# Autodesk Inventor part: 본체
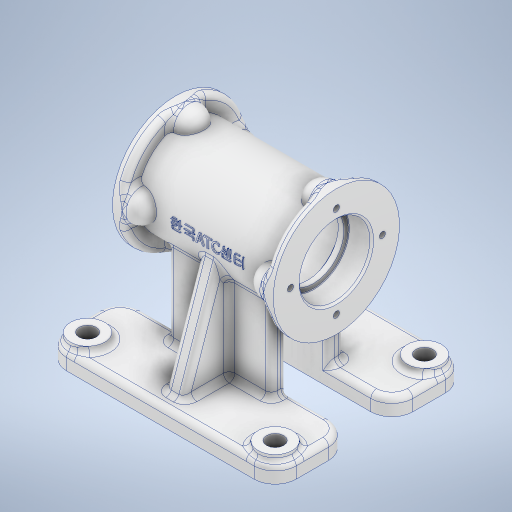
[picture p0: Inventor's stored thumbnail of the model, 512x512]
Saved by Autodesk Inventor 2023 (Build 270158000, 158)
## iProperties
Created: 2026-06
Part Number: 본체
Material: 알루미늄 6061
Document SubType Name: Modeling
Designer: home
Density: 2.7 g/cm^3
Appearance: 알루미늄 - 평지
Mass: 608.577 g
Surface Area: 672.753 cm^2
Volume: 225.399 cm^3
Author: home
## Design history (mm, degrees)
sketch "스케치1"
  geometry: L1 (0, 0)-(-75.914, 0); L2 (-42, 0)-(-42, 33); L3 (-42, 33)-(-37, 33); L4 (-37, 33)-(-37, 25); L5 (-37, 25)-(0, 25); L6 (0, 0)-(0, 52.72); L7 (37, 25)-(0, 25); L8 (37, 33)-(37, 25); L9 (42, 33)-(37, 33); L10 (42, 0)-(42, 33); L11 (-42, 18.5)-(-30, 18.5); L12 (-30, 18.5)-(-30, 16); L13 (-30, 16)-(-27, 16); L14 (-27, 16)-(-27, 20); L15 (-27, 20)-(0, 20); L16 (27, 20)-(0, 20); L17 (27, 16)-(27, 20); L18 (30, 16)-(27, 16); L19 (30, 18.5)-(30, 16); L20 (42, 18.5)-(30, 18.5); 1 further point
  constraints: 40 end point, 9 symmetric about line, 7 perpendicular, 3 point on line, 2 horizontal, 2 vertical
  dimensions: "d0" = 66 diameter of L3 L1; "d1" = 5 distance of L2.end L3.end; "d2" = 50 diameter of L5 L1; "d3" = 42 distance between parallel lines of L6 L2; "d4" = 12 distance of L11.start L11.end; "d6" = 27 distance of L14.end L15.end; "d7" = 37 diameter of L11 L1; "d8" = 32 diameter of L13 L1; "d9" = 40 diameter of L15 L1
revolve "회전1" sketch "스케치1" stored, may be unused: angle "d10" = 90 deg
sketch "스케치2"
  geometry: L1 (37, 25)-(-37, 25) reference; L2 (-37, 33)-(-37, -33) reference; L3 (-37.099, 34.348)-(-37, 34.348); L4 (-37, 33)-(-35, 33); L5 (-27, 25)-(-27, 25); A1 r 8 centre (-35, 25) between (-27, 25) and (-35, 33); 2 further points
  constraints: 6 end point, 2 perpendicular, 2 point on circle, 2 point on line, 2 tangent, 1 centre point, 1 horizontal
  dimensions: "d14" = 8 radius of A1 (derived); "d15" = 10 distance from line of L2 L5.end
revolve "회전2" sketch "스케치2" stored, may be unused: angle "d16" = 210 deg
node "작업 평면1"
sketch "스케치3"
  geometry: L1 (60, -50)-(-60, -50); L2 (-60, -50)-(-60, -11); L3 (-60, -11)-(60, -11); L4 (60, -11)-(60, -50); 2 further points
  constraints: 8 end point, 2 parallel, 1 horizontal, 1 midpoint, 1 perpendicular, 1 vertical alignment
  dimensions: "d21" = 120 distance of L1.start L1.end; "d22" = 39 distance of L3.end L1.start; "d41" = 50 distance from line of point (0, 0) L1
extrude "돌출1" join sketch "스케치3" distance "d23" = 9; taper "d24" = 0 deg
sketch "스케치4"
  geometry: L1 (60, 11)-(60, 50) reference; L2 (60, 50)-(-60, 50) reference; C1 r 9 at (49, 39); 1 further point
  constraints: 1 centre point
  dimensions: "d27" = 11 distance from line of L1 C1.centre; "d28" = 11 distance from line of L2 C1.centre; "d29" = 18 diameter of C1
extrude "돌출2" join sketch "스케치4" distance "d30" = 3; taper "d31" = 0 deg
fillet "모깎기1" dims "d32" = 11
sketch "스케치5"
  geometry: C1 r 9 at (0, 0) reference; 2 further points
  constraints: 1 coincident
hole "구멍1" sketch "스케치5" at (0, 0) diameter "d33" = 9; stored, may be unused: countersink angle "d37" = 90 deg, drill point angle "d39" = 0 deg; dims "d34" = 8, "d35" = 4, "d36" = 2, "d38" = 10
fillet "모깎기2" dims "d40" = 11
sketch "스케치7"
  geometry: L1 (0, 39)-(98, 39) reference; L2 (0, 39)-(98, 39) reference; L3 (22, 39)-(76, 39); L4 (76, 39)-(76, 31); L5 (76, 31)-(22, 31); L6 (22, 31)-(22, 39); 4 further points
  constraints: 8 end point, 2 parallel, 1 horizontal, 1 midpoint, 1 perpendicular, 1 point on line, 1 vertical alignment
  dimensions: "d47" = 8 distance of L5.end L3.start; "d48" = 54 distance of L4.end L5.end
extrude "돌출4" join sketch "스케치7" stored distance "d49" = 10; taper "d50" = 0 deg
sketch "스케치8"
  geometry: L1 (-61, -22)-(-61, -39) reference; L2 (-61, -19)-(-16.248, -19) reference; L3 (-6.346, -24.181)-(-61, -43); L4 (-61, -30)-(-61, -48) reference; L5 (-70, -50)-(-61, -50) reference; L6 (-61, -43)-(-61, -19); L7 (-61, -11)-(-61, -22) reference; L8 (-61, -19)-(-61, -11) reference; L9 (-61, -19)-(-16.248, -19); A1 r 25 centre (0, 0) between (-7.897, 23.72) and (-23.72, 7.897) reference; A2 r 25 centre (0, 0) between (-22.45, -11) and (-16.248, -19) reference; A3 r 25 centre (0, 0) between (-6.346, -24.181) and (-7.897, 23.72); 5 further points
  constraints: 6 end point, 2 point on circle, 1 centre point, 1 coincident, 1 collinear, 1 point on line
  dimensions: "d52" = 7 distance from line of L5 L3.end; "d53" = 19 deg angle of L2 L3
extrude "돌출5" join sketch "스케치8" stored distance "d54" = 10; taper "d55" = 0 deg
sketch "스케치9"
  geometry: L1 (0, 0)-(0, 24); C1 r 33 at (0, 0) reference
  constraints: 2 end point, 1 vertical
  dimensions: "d56" = 24 distance of L1.start L1.end
hole "구멍2" sketch "스케치9" at (0, 24) diameter "d57" = 3.242; stored, may be unused: countersink angle "d61" = 90 deg, drill point angle "d63" = 118 deg; dims "d58" = 8, "d59" = 4, "d60" = 2, "d62" = 10
fillet "모깎기4" dims "d67" = 3
sketch "스케치10"
  geometry: L1 (-64, 11)-(-22.45, 11) reference; L2 (-50, 11)-(-50, -11); L3 (-64, -11)-(-22.45, -11) reference; L4 (-50, 11)-(-22.45, 11); L5 (-22.45, -11)-(-50, -11); L6 (-70, 11)-(-70, 22) reference; A1 r 25 centre (0, 0) between (-16.248, 19) and (-22.45, 11) reference; A2 r 25 centre (0, 0) between (-22.45, -11) and (-16.248, -19) reference; 3 further points
  constraints: 6 end point, 2 point on line, 1 coincident, 1 collinear, 1 horizontal, 1 vertical, 3 other
  dimensions: "d68" = 20 distance between parallel lines of L6 L2
extrude "돌출6" join sketch "스케치10" stored distance "d69" = 10; taper "d70" = 0 deg
fillet "모깎기5" dims "d71" = 3
fillet "모깎기6" dims "d72" = 3
fillet "모깎기7" dims "d73" = 3
fillet "모깎기8" dims "d74" = 3
fillet "모깎기9" dims "d75" = 3
fillet "모깎기10" dims "d76" = 3
fillet "모깎기11" dims "d77" = 3
node "작업 평면2"
sketch "스케치11"
  geometry: L1 (-12.769, 7.739)-(12.769, 7.739); L2 (12.769, 7.739)-(12.769, -7.739); L3 (12.769, -7.739)-(-12.769, -7.739); L4 (-12.769, -7.739)-(-12.769, 7.739); 3 further points
  constraints: 2 midpoint, 1 horizontal alignment, 1 vertical alignment, 2 other
feature "엠보싱1" sketch "스케치11" dims "d80" = 0.5, "d81" = 0
fillet "모깎기13" dims "d82" = 0.3
fillet "모깎기14" dims "d83" = 3
chamfer "모따기1" distance "d84" = 1; stored, may be unused: second distance "d85" = 2, angle "d86" = 45 deg
node "솔리드1"
pattern_circular "원형 패턴1" dims angle "d18" = 360 deg
mirror "미러1"
mirror "미러2"
mirror "미러3"
mirror "미러4"
mirror "미러5"
pattern_circular "원형 패턴2" dims angle "d65" = 360 deg
mirror "미러6"
feature "A9D066F2-1C7D-4E18-AEED-F7BC21143FA4" dims "d33" = 9, "d34" = 8, "d35" = 4, "d36" = 2, "d37" = 90 deg, "d38" = 10, "d39" = 0
other parameters: "d79" = 72.75
